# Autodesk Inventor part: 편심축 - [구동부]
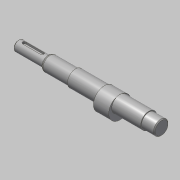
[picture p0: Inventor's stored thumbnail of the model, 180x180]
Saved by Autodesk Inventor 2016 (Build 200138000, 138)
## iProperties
Created: 2017-08
Part Number: 편심축 - [구동부]
Material: 강철, 연강
Document SubType Name: Modeling
Designer: mduedu
Density: 7.86 g/cm^3
Mass: 338.4 g
Surface Area: 105.4 cm^2
Volume: 43.0534 cm^3
Appearance: 강철
Author: mduedu
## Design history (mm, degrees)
sketch "스케치1"
  geometry: L1 (0, 0)-(168, 0); L2 (168, 0)-(168, 8.5); L3 (168, 8.5)-(153, 8.5); L4 (153, 8.5)-(153, 9.5); L5 (153, 9.5)-(67, 9.5); L6 (67, 9.5)-(67, 8.5); L7 (67, 8.5)-(35, 8.5); L8 (35, 8.5)-(35, 6); L9 (35, 6)-(0, 6); L10 (0, 6)-(0, 0)
  constraints: 20 end point, 6 parallel, 2 collinear, 2 perpendicular, 1 horizontal
  dimensions: "d0" = 168 distance of L1.start L1.end; "d1" = 17 diameter of L3 L1; "d2" = 19 diameter of L5 L1; "d3" = 12 diameter of L9 L1; "d4" = 35 distance of L8.end L9.end; "d5" = 15 distance of L2.end L3.end; "d6" = 86 distance of L4.end L5.end
revolve "회전1" sketch "스케치1" stored, may be unused: angle "d7" = 90 deg
node "작업 평면1"
sketch "스케치2"
  geometry: C1 r 9.5 at (0, 0) reference; C2 r 13 at (0, -3.5); 1 further point
  constraints: 1 centre point, 1 tangent, 1 vertical alignment
  dimensions: "d8" = 3.5 distance of point (0, 0) C2.centre
extrude "돌출1" join sketch "스케치2" stored distance "d9" = 18; taper "d10" = 0 deg
chamfer "모따기1" distance "d11" = 1; stored, may be unused: second distance "d12" = 2, angle "d13" = 45 deg
node "작업 평면2"
sketch "스케치3"
  geometry: L1 (10.5, -2)-(-10.5, -2); L2 (-10.5, -2)-(-10.5, 2); L3 (-10.5, 2)-(10.5, 2); L4 (10.5, 2)-(10.5, -2); L5 (17.5, 6)-(17.5, -6) reference; L6 (-17.5, 8.5)-(-17.5, -8.5) reference; A1 r 2 centre (10.5, 0) between (10.5, -2) and (10.5, 2); A2 r 2 centre (-10.5, 0) between (-10.5, 2) and (-10.5, -2); A3 r 2 centre (10.5, 0) between (10.5, 2) and (10.5, -2); A4 r 2 centre (-10.5, 0) between (-10.5, -2) and (-10.5, 2); 1 further point
  constraints: 8 end point, 8 point on circle, 4 centre point, 2 midpoint, 2 parallel, 1 horizontal, 1 horizontal alignment, 1 perpendicular
  dimensions: "d14" = 25 dimension on A2 A1; "d16" = 4 distance between parallel lines of L3 L1; "d17" = 5 distance edge to line of A1 L5; "d46" = 5 distance edge to line of A2 L6 (derived)
extrude "돌출2" cut sketch "스케치3" distance "d18" = 2.5; taper "d19" = 0 deg
chamfer "모따기2" distance "d20" = 1; stored, may be unused: second distance "d21" = 2, angle "d22" = 45 deg
chamfer "모따기4" distance "d39" = 1.82; stored, may be unused: second distance "d40" = 2, angle "d41" = 30 deg
fillet "모깎기4" dims "d45" = 2
hole "구멍1" diameter "d29" = 3.242; stored, may be unused: countersink angle "d33" = 90 deg, drill point angle "d35" = 118 deg; dims "d30" = 8, "d31" = 4, "d32" = 2, "d34" = 10, "d36" = 10, "d37" = 10
node "솔리드1"
node "절단 모서리 투영1"
